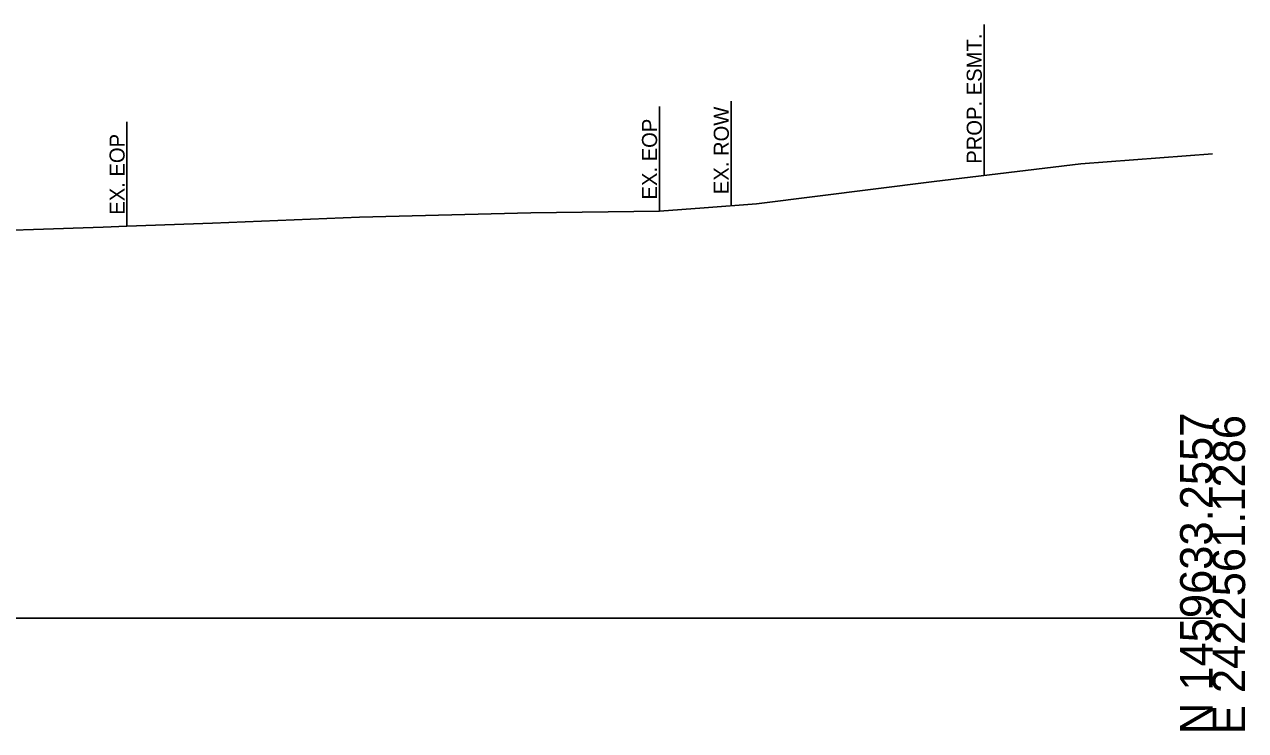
# Model space of a CAD drawing. Extents: x -26 to 403, y -13 to 3053.
# Drawn here: x 297.7 to 402.8, y 2490.3 to 2551.1 of the extents above; entities that cross this region are included whole.
import ezdxf

# ---------------------------------------------------------------- set-up
doc = ezdxf.new("R2010")
doc.units = 0
for name, color, linetype in [('8', 7, 'Continuous'), ('DTM_X_GROUND', 7, 'Continuous'), ('ROW_EASEMENTS', 7, 'Continuous'), ('X_ROW', 7, 'Continuous'), ('X_ROW_TX', 7, 'Continuous'), ('X_TRANS_EOP', 7, 'Continuous'), ('XS_CELL', 7, 'Continuous')]:
    doc.layers.add(name, color=color, linetype=linetype)

msp = doc.modelspace()

# ---------------------------------------------------------------- linework, layer by layer
at = {"layer": 'DTM_X_GROUND'}
msp.add_lwpolyline([(109.45, 2513.33), (131.53, 2514.24), (145.37, 2514.58), (172.2, 2514.57), (196.87, 2516.02), (224.6, 2518.56), (225.93, 2518.49), (229.29, 2518.88), (231.43, 2519.16), (275.47, 2529.21), (294.91, 2533.34), (298.45, 2533.45), (304.45, 2533.67), (306.49, 2533.73), (313.87, 2534), (326.53, 2534.53), (341.29, 2534.88), (352.35, 2535.04), (356.21, 2535.32), (360.71, 2535.67), (376.02, 2537.6), (388.64, 2539.12), (400, 2539.97)], dxfattribs=at)
at = {"layer": 'ROW_EASEMENTS'}
msp.add_line((380.32, 2551.12), (380.32, 2538.12), dxfattribs=at)
at = {"layer": 'X_ROW'}
msp.add_line((358.53, 2544.5), (358.53, 2535.5), dxfattribs=at)
at = {"layer": 'X_TRANS_EOP'}
for p, q in [((352.35, 2544.04), (352.35, 2535.04)), ((306.49, 2542.73), (306.49, 2533.73))]:
    msp.add_line(p, q, dxfattribs=at)
at = {"layer": 'XS_CELL'}
msp.add_line((200, 2500), (400, 2500), dxfattribs=at)

# ---------------------------------------------------------------- texts
at = {"layer": '8'}
msp.add_text('X', height=0.012, dxfattribs=at).set_placement((300.68, 2533.52))
at = {"layer": 'ROW_EASEMENTS'}
msp.add_text('PROP. ESMT.', height=1.3, rotation=90, dxfattribs=at).set_placement((380.12, 2539.12))
at = {"layer": 'X_ROW_TX'}
msp.add_text('EX. ROW', height=1.3, rotation=90, dxfattribs=at).set_placement((358.33, 2536.5))
at = {"layer": 'X_TRANS_EOP'}
for p in [(352.15, 2536.04), (306.29, 2534.73)]:
    msp.add_text('EX. EOP', height=1.3, rotation=90, dxfattribs=at).set_placement(p)
at = {"layer": 'XS_CELL'}
for s, p in [('N 1459633.2557', (400, 2490)), ('E 2422561.1286', (402.8, 2490))]:
    msp.add_text(s, height=2.8, rotation=90, dxfattribs=at).set_placement(p)

doc.saveas('drawing.dxf')
